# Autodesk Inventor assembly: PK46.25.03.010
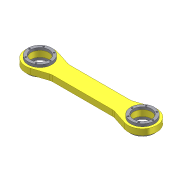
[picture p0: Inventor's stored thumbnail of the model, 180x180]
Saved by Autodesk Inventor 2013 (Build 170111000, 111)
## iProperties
Created: 2005-04
Part Number: PK46.25.03.010
Document SubType Name: Assembly
Designer: salex
Manufacturer: Standard
Standards Organization: Custom
Author: salex
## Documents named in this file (3)
- D:\FrontLoaderVault\Data\Assy, Chassis, Front\PK46.25.03.010.iam
- D:\FrontLoaderVault\Data\Assy, Chassis, Front\PK46.25.03.001.ipt
- D:\FrontLoaderVault\Data\Assy, Chassis, Front\PK46.25.01.004.ipt
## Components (5 placed, 2 different names)
1. PK46.25.03.001:1 — Insert:1, Insert:2, Insert:3, Insert:4
2. PK46.25.01.004:1 — Insert:1
3. PK46.25.01.004:2 — Insert:3
4. PK46.25.01.004:3 — Insert:2
5. PK46.25.01.004:4 — Insert:4
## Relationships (4: Insert 4)
- Insert:1: PK46.25.03.001:1 ↔ PK46.25.01.004:1
- Insert:2: PK46.25.03.001:1 ↔ PK46.25.01.004:3
- Insert:3: PK46.25.03.001:1 ↔ PK46.25.01.004:2
- Insert:4: PK46.25.03.001:1 ↔ PK46.25.01.004:4
